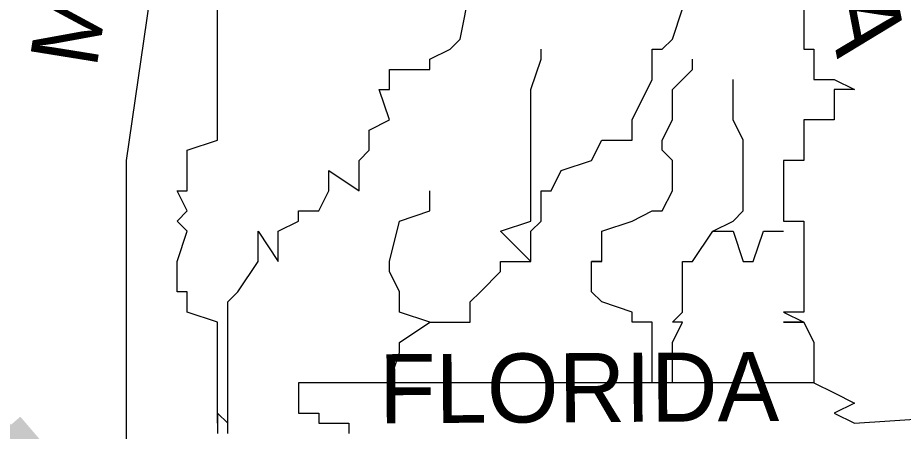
# Model space of a CAD drawing. Extents: x -12822 to 16384, y -6351 to 1913.
# Drawn here: x 65.86 to 88.88, y -3310.91 to -3300.17 of the extents above; entities that cross this region are included whole.
import ezdxf

# ---------------------------------------------------------------- set-up
doc = ezdxf.new("R2010")
doc.units = 0
doc.layers.add('great seal', color=7, linetype='Continuous')

msp = doc.modelspace()

# ---------------------------------------------------------------- linework, layer by layer
at = {"layer": 'great seal'}
for points in [[(68.693, -3313.071), (68.693, -3303.874), (71.058, -3287.583)], [(68.693, -3313.071), (68.693, -3303.874), (71.058, -3287.583)], [(68.693, -3313.071), (68.693, -3303.874), (71.058, -3287.583)], [(79.204, -3306.502), (79.204, -3306.502), (79.204, -3305.714), (79.467, -3305.451), (79.467, -3305.188), (79.467, -3304.663), (79.729, -3304.663), (79.992, -3304.137), (80.78, -3303.874), (81.043, -3303.349), (81.832, -3303.349), (81.832, -3302.823), (82.357, -3301.772), (82.357, -3301.247), (82.357, -3301.247), (82.357, -3300.984), (82.62, -3300.984), (82.883, -3300.721), (83.145, -3299.933), (83.934, -3299.407), (84.459, -3299.145), (84.459, -3298.882), (84.459, -3298.619), (83.934, -3298.619)], [(79.204, -3306.502), (79.204, -3306.502), (79.204, -3305.714), (79.467, -3305.451), (79.467, -3305.188), (79.467, -3304.663), (79.729, -3304.663), (79.992, -3304.137), (80.78, -3303.874), (81.043, -3303.349), (81.832, -3303.349), (81.832, -3302.823), (82.357, -3301.772), (82.357, -3301.247), (82.357, -3301.247), (82.357, -3300.984), (82.62, -3300.984), (82.883, -3300.721), (83.145, -3299.933), (83.934, -3299.407), (84.459, -3299.145), (84.459, -3298.882), (84.459, -3298.619), (83.934, -3298.619)], [(79.204, -3306.502), (79.204, -3306.502), (79.204, -3305.714), (79.467, -3305.451), (79.467, -3305.188), (79.467, -3304.663), (79.729, -3304.663), (79.992, -3304.137), (80.78, -3303.874), (81.043, -3303.349), (81.832, -3303.349), (81.832, -3302.823), (82.357, -3301.772), (82.357, -3301.247), (82.357, -3301.247), (82.357, -3300.984), (82.62, -3300.984), (82.883, -3300.721), (83.145, -3299.933), (83.934, -3299.407), (84.459, -3299.145), (84.459, -3298.882), (84.459, -3298.619), (83.934, -3298.619)], [(71.321, -3310.706), (71.321, -3310.443), (71.321, -3309.918), (71.321, -3309.918), (71.321, -3308.867), (71.321, -3308.604), (71.321, -3308.078), (71.321, -3308.078), (71.321, -3307.816), (71.321, -3307.553), (71.584, -3307.29), (72.109, -3306.502), (72.109, -3305.714), (72.635, -3306.502), (72.635, -3305.714), (73.16, -3305.451), (73.16, -3305.188), (73.686, -3305.188), (73.949, -3304.663), (73.949, -3304.137), (74.737, -3304.663), (74.737, -3303.874), (75, -3303.611), (75, -3303.349), (75, -3303.086), (75.525, -3302.823), (75.262, -3302.035), (75.525, -3302.035), (75.525, -3301.509), (76.576, -3301.509), (76.576, -3301.247), (76.576, -3301.247), (77.102, -3300.984), (77.365, -3300.721), (77.627, -3299.407)], [(71.321, -3310.706), (71.321, -3310.443), (71.321, -3309.918), (71.321, -3309.918), (71.321, -3308.867), (71.321, -3308.604), (71.321, -3308.078), (71.321, -3308.078), (71.321, -3307.816), (71.321, -3307.553), (71.584, -3307.29), (72.109, -3306.502), (72.109, -3305.714), (72.635, -3306.502), (72.635, -3305.714), (73.16, -3305.451), (73.16, -3305.188), (73.686, -3305.188), (73.949, -3304.663), (73.949, -3304.137), (74.737, -3304.663), (74.737, -3303.874), (75, -3303.611), (75, -3303.349), (75, -3303.086), (75.525, -3302.823), (75.262, -3302.035), (75.525, -3302.035), (75.525, -3301.509), (76.576, -3301.509), (76.576, -3301.247), (76.576, -3301.247), (77.102, -3300.984), (77.365, -3300.721), (77.627, -3299.407)], [(71.321, -3310.706), (71.321, -3310.443), (71.321, -3309.918), (71.321, -3309.918), (71.321, -3308.867), (71.321, -3308.604), (71.321, -3308.078), (71.321, -3308.078), (71.321, -3307.816), (71.321, -3307.553), (71.584, -3307.29), (72.109, -3306.502), (72.109, -3305.714), (72.635, -3306.502), (72.635, -3305.714), (73.16, -3305.451), (73.16, -3305.188), (73.686, -3305.188), (73.949, -3304.663), (73.949, -3304.137), (74.737, -3304.663), (74.737, -3303.874), (75, -3303.611), (75, -3303.349), (75, -3303.086), (75.525, -3302.823), (75.262, -3302.035), (75.525, -3302.035), (75.525, -3301.509), (76.576, -3301.509), (76.576, -3301.247), (76.576, -3301.247), (77.102, -3300.984), (77.365, -3300.721), (77.627, -3299.407)], [(71.058, -3310.706), (71.058, -3310.443), (71.058, -3309.918), (71.058, -3309.918), (71.058, -3309.655), (71.058, -3309.655), (71.058, -3308.604), (71.058, -3308.078), (71.058, -3308.078), (70.27, -3307.816), (70.27, -3307.553), (70.27, -3307.29), (70.007, -3307.29), (70.007, -3306.502), (70.007, -3306.502), (70.27, -3305.714), (70.007, -3305.451), (70.27, -3305.188), (70.007, -3304.663), (70.007, -3304.663), (70.007, -3304.663), (70.27, -3304.663), (70.27, -3303.874), (70.27, -3303.874), (70.27, -3303.611), (71.058, -3303.349), (71.058, -3303.086), (71.058, -3302.823), (71.058, -3302.035), (71.058, -3301.772), (71.058, -3301.247), (71.058, -3301.247), (71.058, -3300.984), (71.058, -3299.933)], [(71.058, -3310.706), (71.058, -3310.443), (71.058, -3309.918), (71.058, -3309.918), (71.058, -3309.655), (71.058, -3309.655), (71.058, -3308.604), (71.058, -3308.078), (71.058, -3308.078), (70.27, -3307.816), (70.27, -3307.553), (70.27, -3307.29), (70.007, -3307.29), (70.007, -3306.502), (70.007, -3306.502), (70.27, -3305.714), (70.007, -3305.451), (70.27, -3305.188), (70.007, -3304.663), (70.007, -3304.663), (70.007, -3304.663), (70.27, -3304.663), (70.27, -3303.874), (70.27, -3303.874), (70.27, -3303.611), (71.058, -3303.349), (71.058, -3303.086), (71.058, -3302.823), (71.058, -3302.035), (71.058, -3301.772), (71.058, -3301.247), (71.058, -3301.247), (71.058, -3300.984), (71.058, -3299.933)], [(71.058, -3310.706), (71.058, -3310.443), (71.058, -3309.918), (71.058, -3309.918), (71.058, -3309.655), (71.058, -3309.655), (71.058, -3308.604), (71.058, -3308.078), (71.058, -3308.078), (70.27, -3307.816), (70.27, -3307.553), (70.27, -3307.29), (70.007, -3307.29), (70.007, -3306.502), (70.007, -3306.502), (70.27, -3305.714), (70.007, -3305.451), (70.27, -3305.188), (70.007, -3304.663), (70.007, -3304.663), (70.007, -3304.663), (70.27, -3304.663), (70.27, -3303.874), (70.27, -3303.874), (70.27, -3303.611), (71.058, -3303.349), (71.058, -3303.086), (71.058, -3302.823), (71.058, -3302.035), (71.058, -3301.772), (71.058, -3301.247), (71.058, -3301.247), (71.058, -3300.984), (71.058, -3299.933)], [(86.299, -3299.933), (86.299, -3300.721), (86.299, -3300.984), (86.561, -3300.984), (86.561, -3301.247), (86.561, -3301.247), (86.561, -3301.509), (86.561, -3301.772), (87.087, -3301.772), (87.612, -3302.035), (87.087, -3302.035), (87.087, -3302.823), (87.087, -3302.823), (86.561, -3302.823), (86.561, -3302.823), (86.561, -3302.823), (86.561, -3302.823), (86.299, -3302.823), (86.299, -3302.823), (86.299, -3302.823), (86.299, -3303.086), (86.299, -3303.349), (86.299, -3303.349), (86.299, -3303.349), (86.299, -3303.349), (86.299, -3303.349), (86.299, -3303.611), (86.299, -3303.611), (86.299, -3303.611), (86.299, -3303.874), (86.299, -3303.874), (85.773, -3303.874), (85.773, -3303.874), (85.773, -3303.874), (85.773, -3304.137), (85.773, -3304.137), (85.773, -3304.663), (85.773, -3304.663), (85.773, -3304.663), (85.773, -3304.663), (85.773, -3304.663), (85.773, -3304.663), (85.773, -3304.663), (85.773, -3305.188), (85.773, -3305.188), (85.773, -3305.188), (85.773, -3305.188), (85.773, -3305.188), (85.773, -3305.188), (85.773, -3305.451), (86.299, -3305.451), (86.299, -3305.714), (86.299, -3305.714), (86.299, -3305.714), (86.299, -3306.502), (86.299, -3306.502), (86.299, -3306.502), (86.299, -3306.502), (86.299, -3306.502), (86.299, -3306.502), (86.299, -3306.765), (86.299, -3307.29), (86.299, -3307.29), (86.299, -3307.29), (86.299, -3307.553), (86.299, -3307.553), (86.299, -3307.816), (86.299, -3307.816), (85.773, -3307.816), (85.773, -3307.816), (85.773, -3307.816), (85.773, -3307.816), (86.299, -3308.078), (86.299, -3308.078), (85.773, -3308.078), (86.299, -3308.078), (86.299, -3308.078), (86.299, -3308.078), (86.561, -3308.604), (86.561, -3308.604), (86.561, -3308.867), (86.561, -3308.867), (86.561, -3309.655), (73.16, -3309.655), (73.16, -3309.918), (73.16, -3309.918)], [(86.299, -3299.933), (86.299, -3300.721), (86.299, -3300.984), (86.561, -3300.984), (86.561, -3301.247), (86.561, -3301.247), (86.561, -3301.509), (86.561, -3301.772), (87.087, -3301.772), (87.612, -3302.035), (87.087, -3302.035), (87.087, -3302.823), (87.087, -3302.823), (86.561, -3302.823), (86.561, -3302.823), (86.561, -3302.823), (86.561, -3302.823), (86.299, -3302.823), (86.299, -3302.823), (86.299, -3302.823), (86.299, -3303.086), (86.299, -3303.349), (86.299, -3303.349), (86.299, -3303.349), (86.299, -3303.349), (86.299, -3303.349), (86.299, -3303.611), (86.299, -3303.611), (86.299, -3303.611), (86.299, -3303.874), (86.299, -3303.874), (85.773, -3303.874), (85.773, -3303.874), (85.773, -3303.874), (85.773, -3304.137), (85.773, -3304.137), (85.773, -3304.663), (85.773, -3304.663), (85.773, -3304.663), (85.773, -3304.663), (85.773, -3304.663), (85.773, -3304.663), (85.773, -3304.663), (85.773, -3305.188), (85.773, -3305.188), (85.773, -3305.188), (85.773, -3305.188), (85.773, -3305.188), (85.773, -3305.188), (85.773, -3305.451), (86.299, -3305.451), (86.299, -3305.714), (86.299, -3305.714), (86.299, -3305.714), (86.299, -3306.502), (86.299, -3306.502), (86.299, -3306.502), (86.299, -3306.502), (86.299, -3306.502), (86.299, -3306.502), (86.299, -3306.765), (86.299, -3307.29), (86.299, -3307.29), (86.299, -3307.29), (86.299, -3307.553), (86.299, -3307.553), (86.299, -3307.816), (86.299, -3307.816), (85.773, -3307.816), (85.773, -3307.816), (85.773, -3307.816), (85.773, -3307.816), (86.299, -3308.078), (86.299, -3308.078), (85.773, -3308.078), (86.299, -3308.078), (86.299, -3308.078), (86.299, -3308.078), (86.561, -3308.604), (86.561, -3308.604), (86.561, -3308.867), (86.561, -3308.867), (86.561, -3309.655), (73.16, -3309.655), (73.16, -3309.918), (73.16, -3309.918)], [(86.299, -3299.933), (86.299, -3300.721), (86.299, -3300.984), (86.561, -3300.984), (86.561, -3301.247), (86.561, -3301.247), (86.561, -3301.509), (86.561, -3301.772), (87.087, -3301.772), (87.612, -3302.035), (87.087, -3302.035), (87.087, -3302.823), (87.087, -3302.823), (86.561, -3302.823), (86.561, -3302.823), (86.561, -3302.823), (86.561, -3302.823), (86.299, -3302.823), (86.299, -3302.823), (86.299, -3302.823), (86.299, -3303.086), (86.299, -3303.349), (86.299, -3303.349), (86.299, -3303.349), (86.299, -3303.349), (86.299, -3303.349), (86.299, -3303.611), (86.299, -3303.611), (86.299, -3303.611), (86.299, -3303.874), (86.299, -3303.874), (85.773, -3303.874), (85.773, -3303.874), (85.773, -3303.874), (85.773, -3304.137), (85.773, -3304.137), (85.773, -3304.663), (85.773, -3304.663), (85.773, -3304.663), (85.773, -3304.663), (85.773, -3304.663), (85.773, -3304.663), (85.773, -3304.663), (85.773, -3305.188), (85.773, -3305.188), (85.773, -3305.188), (85.773, -3305.188), (85.773, -3305.188), (85.773, -3305.188), (85.773, -3305.451), (86.299, -3305.451), (86.299, -3305.714), (86.299, -3305.714), (86.299, -3305.714), (86.299, -3306.502), (86.299, -3306.502), (86.299, -3306.502), (86.299, -3306.502), (86.299, -3306.502), (86.299, -3306.502), (86.299, -3306.765), (86.299, -3307.29), (86.299, -3307.29), (86.299, -3307.29), (86.299, -3307.553), (86.299, -3307.553), (86.299, -3307.816), (86.299, -3307.816), (85.773, -3307.816), (85.773, -3307.816), (85.773, -3307.816), (85.773, -3307.816), (86.299, -3308.078), (86.299, -3308.078), (85.773, -3308.078), (86.299, -3308.078), (86.299, -3308.078), (86.299, -3308.078), (86.561, -3308.604), (86.561, -3308.604), (86.561, -3308.867), (86.561, -3308.867), (86.561, -3309.655), (73.16, -3309.655), (73.16, -3309.918), (73.16, -3309.918)], [(76.576, -3308.078), (76.576, -3308.078), (77.102, -3308.078), (77.365, -3308.078), (77.627, -3308.078), (77.627, -3307.816), (77.627, -3307.553), (77.89, -3307.29), (78.416, -3306.765), (78.416, -3306.502), (79.204, -3306.502), (79.204, -3306.502), (78.416, -3305.714), (79.204, -3305.451), (79.204, -3305.188), (79.204, -3304.663), (79.204, -3304.137), (79.204, -3303.874), (79.204, -3303.349), (79.204, -3303.349), (79.204, -3302.823), (79.204, -3302.035), (79.467, -3301.247), (79.467, -3301.247), (79.467, -3300.984)], [(76.576, -3308.078), (76.576, -3308.078), (77.102, -3308.078), (77.365, -3308.078), (77.627, -3308.078), (77.627, -3307.816), (77.627, -3307.553), (77.89, -3307.29), (78.416, -3306.765), (78.416, -3306.502), (79.204, -3306.502), (79.204, -3306.502), (78.416, -3305.714), (79.204, -3305.451), (79.204, -3305.188), (79.204, -3304.663), (79.204, -3304.137), (79.204, -3303.874), (79.204, -3303.349), (79.204, -3303.349), (79.204, -3302.823), (79.204, -3302.035), (79.467, -3301.247), (79.467, -3301.247), (79.467, -3300.984)], [(76.576, -3308.078), (76.576, -3308.078), (77.102, -3308.078), (77.365, -3308.078), (77.627, -3308.078), (77.627, -3307.816), (77.627, -3307.553), (77.89, -3307.29), (78.416, -3306.765), (78.416, -3306.502), (79.204, -3306.502), (79.204, -3306.502), (78.416, -3305.714), (79.204, -3305.451), (79.204, -3305.188), (79.204, -3304.663), (79.204, -3304.137), (79.204, -3303.874), (79.204, -3303.349), (79.204, -3303.349), (79.204, -3302.823), (79.204, -3302.035), (79.467, -3301.247), (79.467, -3301.247), (79.467, -3300.984)], [(82.357, -3309.655), (82.357, -3308.867), (82.357, -3308.604), (82.357, -3308.078), (82.357, -3308.078), (81.832, -3308.078), (81.832, -3307.816), (81.043, -3307.553), (80.78, -3307.29), (80.78, -3306.765), (80.78, -3306.502), (81.043, -3306.502), (80.78, -3306.502), (81.043, -3306.502), (81.043, -3305.714), (81.832, -3305.451), (82.357, -3305.188), (82.357, -3305.188), (82.62, -3305.188), (82.883, -3304.663), (82.883, -3304.663), (82.883, -3304.137), (82.883, -3303.874), (82.883, -3303.874), (82.62, -3303.611), (82.62, -3303.349), (82.883, -3302.823), (82.883, -3302.035), (83.145, -3301.772), (83.408, -3301.509), (83.408, -3301.247)], [(82.357, -3309.655), (82.357, -3308.867), (82.357, -3308.604), (82.357, -3308.078), (82.357, -3308.078), (81.832, -3308.078), (81.832, -3307.816), (81.043, -3307.553), (80.78, -3307.29), (80.78, -3306.765), (80.78, -3306.502), (81.043, -3306.502), (80.78, -3306.502), (81.043, -3306.502), (81.043, -3305.714), (81.832, -3305.451), (82.357, -3305.188), (82.357, -3305.188), (82.62, -3305.188), (82.883, -3304.663), (82.883, -3304.663), (82.883, -3304.137), (82.883, -3303.874), (82.883, -3303.874), (82.62, -3303.611), (82.62, -3303.349), (82.883, -3302.823), (82.883, -3302.035), (83.145, -3301.772), (83.408, -3301.509), (83.408, -3301.247)], [(82.357, -3309.655), (82.357, -3308.867), (82.357, -3308.604), (82.357, -3308.078), (82.357, -3308.078), (81.832, -3308.078), (81.832, -3307.816), (81.043, -3307.553), (80.78, -3307.29), (80.78, -3306.765), (80.78, -3306.502), (81.043, -3306.502), (80.78, -3306.502), (81.043, -3306.502), (81.043, -3305.714), (81.832, -3305.451), (82.357, -3305.188), (82.357, -3305.188), (82.62, -3305.188), (82.883, -3304.663), (82.883, -3304.663), (82.883, -3304.137), (82.883, -3303.874), (82.883, -3303.874), (82.62, -3303.611), (82.62, -3303.349), (82.883, -3302.823), (82.883, -3302.035), (83.145, -3301.772), (83.408, -3301.509), (83.408, -3301.247)], [(83.934, -3305.714), (83.934, -3305.714), (84.459, -3305.451), (84.722, -3305.188), (84.722, -3305.188), (84.722, -3304.663), (84.722, -3304.137), (84.722, -3303.874), (84.722, -3303.611), (84.722, -3303.349), (84.459, -3302.823), (84.459, -3302.823), (84.459, -3301.772)], [(83.934, -3305.714), (83.934, -3305.714), (84.459, -3305.451), (84.722, -3305.188), (84.722, -3305.188), (84.722, -3304.663), (84.722, -3304.137), (84.722, -3303.874), (84.722, -3303.611), (84.722, -3303.349), (84.459, -3302.823), (84.459, -3302.823), (84.459, -3301.772)], [(83.934, -3305.714), (83.934, -3305.714), (84.459, -3305.451), (84.722, -3305.188), (84.722, -3305.188), (84.722, -3304.663), (84.722, -3304.137), (84.722, -3303.874), (84.722, -3303.611), (84.722, -3303.349), (84.459, -3302.823), (84.459, -3302.823), (84.459, -3301.772)], [(75.525, -3309.655), (75.788, -3308.867), (75.788, -3308.604), (76.576, -3308.078), (76.576, -3308.078), (76.576, -3308.078), (75.788, -3307.816), (75.788, -3307.553), (75.788, -3307.29), (75.525, -3306.765), (75.525, -3306.502), (75.525, -3306.502), (75.788, -3305.451), (76.576, -3305.188), (76.576, -3304.663)], [(75.525, -3309.655), (75.788, -3308.867), (75.788, -3308.604), (76.576, -3308.078), (76.576, -3308.078), (76.576, -3308.078), (75.788, -3307.816), (75.788, -3307.553), (75.788, -3307.29), (75.525, -3306.765), (75.525, -3306.502), (75.525, -3306.502), (75.788, -3305.451), (76.576, -3305.188), (76.576, -3304.663)], [(75.525, -3309.655), (75.788, -3308.867), (75.788, -3308.604), (76.576, -3308.078), (76.576, -3308.078), (76.576, -3308.078), (75.788, -3307.816), (75.788, -3307.553), (75.788, -3307.29), (75.525, -3306.765), (75.525, -3306.502), (75.525, -3306.502), (75.788, -3305.451), (76.576, -3305.188), (76.576, -3304.663)], [(82.883, -3309.655), (82.883, -3308.867), (82.883, -3308.867), (82.883, -3308.604), (83.145, -3308.078), (82.883, -3308.078), (83.145, -3307.816), (83.145, -3307.553), (83.145, -3307.29), (83.145, -3307.29), (83.145, -3306.765), (83.145, -3306.502), (83.408, -3306.502), (83.934, -3305.714), (84.459, -3305.714), (84.722, -3306.502), (84.985, -3306.502), (85.247, -3305.714), (85.51, -3305.714), (85.773, -3305.714)], [(82.883, -3309.655), (82.883, -3308.867), (82.883, -3308.867), (82.883, -3308.604), (83.145, -3308.078), (82.883, -3308.078), (83.145, -3307.816), (83.145, -3307.553), (83.145, -3307.29), (83.145, -3307.29), (83.145, -3306.765), (83.145, -3306.502), (83.408, -3306.502), (83.934, -3305.714), (84.459, -3305.714), (84.722, -3306.502), (84.985, -3306.502), (85.247, -3305.714), (85.51, -3305.714), (85.773, -3305.714)], [(82.883, -3309.655), (82.883, -3308.867), (82.883, -3308.867), (82.883, -3308.604), (83.145, -3308.078), (82.883, -3308.078), (83.145, -3307.816), (83.145, -3307.553), (83.145, -3307.29), (83.145, -3307.29), (83.145, -3306.765), (83.145, -3306.502), (83.408, -3306.502), (83.934, -3305.714), (84.459, -3305.714), (84.722, -3306.502), (84.985, -3306.502), (85.247, -3305.714), (85.51, -3305.714), (85.773, -3305.714)], [(86.561, -3309.655), (87.087, -3309.918), (87.087, -3309.918), (87.612, -3310.181), (87.087, -3310.443), (87.612, -3310.706), (91.554, -3310.443)], [(86.561, -3309.655), (87.087, -3309.918), (87.087, -3309.918), (87.612, -3310.181), (87.087, -3310.443), (87.612, -3310.706), (91.554, -3310.443)], [(86.561, -3309.655), (87.087, -3309.918), (87.087, -3309.918), (87.612, -3310.181), (87.087, -3310.443), (87.612, -3310.706), (91.554, -3310.443)], [(73.16, -3309.918), (73.16, -3310.181), (73.16, -3310.181), (73.16, -3310.443), (73.16, -3310.443), (73.686, -3310.443), (73.686, -3310.443), (73.686, -3310.706), (73.949, -3310.706), (73.949, -3310.706), (73.949, -3310.706), (74.474, -3310.706), (74.474, -3310.706), (74.474, -3310.706), (74.474, -3310.969)], [(73.16, -3309.918), (73.16, -3310.181), (73.16, -3310.181), (73.16, -3310.443), (73.16, -3310.443), (73.686, -3310.443), (73.686, -3310.443), (73.686, -3310.706), (73.949, -3310.706), (73.949, -3310.706), (73.949, -3310.706), (74.474, -3310.706), (74.474, -3310.706), (74.474, -3310.706), (74.474, -3310.969)], [(73.16, -3309.918), (73.16, -3310.181), (73.16, -3310.181), (73.16, -3310.443), (73.16, -3310.443), (73.686, -3310.443), (73.686, -3310.443), (73.686, -3310.706), (73.949, -3310.706), (73.949, -3310.706), (73.949, -3310.706), (74.474, -3310.706), (74.474, -3310.706), (74.474, -3310.706), (74.474, -3310.969)], [(71.321, -3310.969), (71.321, -3310.706), (71.321, -3310.706), (71.321, -3310.706), (71.321, -3310.706), (71.321, -3310.706), (71.321, -3310.706), (71.321, -3310.706), (71.058, -3310.443)], [(71.058, -3310.443), (71.058, -3310.443), (71.058, -3310.706), (71.058, -3310.706), (71.058, -3310.706), (71.058, -3310.706), (71.058, -3310.706), (71.058, -3310.706), (71.058, -3310.969)], [(71.321, -3310.969), (71.321, -3310.706), (71.321, -3310.706), (71.321, -3310.706), (71.321, -3310.706), (71.321, -3310.706), (71.321, -3310.706), (71.321, -3310.706), (71.058, -3310.443)], [(71.058, -3310.443), (71.058, -3310.443), (71.058, -3310.706), (71.058, -3310.706), (71.058, -3310.706), (71.058, -3310.706), (71.058, -3310.706), (71.058, -3310.706), (71.058, -3310.969)], [(71.321, -3310.969), (71.321, -3310.706), (71.321, -3310.706), (71.321, -3310.706), (71.321, -3310.706), (71.321, -3310.706), (71.321, -3310.706), (71.321, -3310.706), (71.058, -3310.443)], [(71.058, -3310.443), (71.058, -3310.443), (71.058, -3310.706), (71.058, -3310.706), (71.058, -3310.706), (71.058, -3310.706), (71.058, -3310.706), (71.058, -3310.706), (71.058, -3310.969)], [(71.321, -3310.706), (71.321, -3310.706)], [(71.321, -3310.706), (71.321, -3310.706)], [(71.321, -3310.706), (71.321, -3310.706)]]:
    msp.add_lwpolyline(points, dxfattribs=at)
for radius in [22.994, 22.994, 22.994, 22.389, 22.389, 22.389, 17.779, 17.779, 17.779, 17.222, 17.222, 17.222]:
    msp.add_circle((77.645, -3299.854), radius, dxfattribs=at)

# ---------------------------------------------------------------- texts
for s, height, rotation, p in [('MISSISSIPPI', 1.75474, 80.8531, (67.905, -3301.509)), ('MISSISSIPPI', 1.75474, 80.8531, (67.905, -3301.509)), ('MISSISSIPPI', 1.75474, 80.8531, (67.905, -3301.509)), ('GEORGIA', 1.8446, 280.9296, (84.985, -3289.948)), ('GEORGIA', 1.8446, 280.9296, (84.985, -3289.948)), ('GEORGIA', 1.8446, 280.9296, (84.985, -3289.948)), ('E', 5.851, 302.3539, (59.234, -3311.494)), ('E', 5.851, 302.3539, (59.234, -3311.494)), ('E', 5.851, 302.3539, (59.234, -3311.494)), ('FLORIDA', 1.7941, 0.3238, (75.262, -3310.706)), ('FLORIDA', 1.7941, 0.3238, (75.262, -3310.706)), ('FLORIDA', 1.7941, 0.3238, (75.262, -3310.706)), ('N', 5.851, 310.6423, (61.073, -3313.859)), ('N', 5.851, 310.6423, (61.073, -3313.859)), ('N', 5.851, 310.6423, (61.073, -3313.859))]:
    msp.add_text(s, height=height, rotation=rotation, dxfattribs=at).set_placement(p)

doc.saveas('drawing.dxf')
